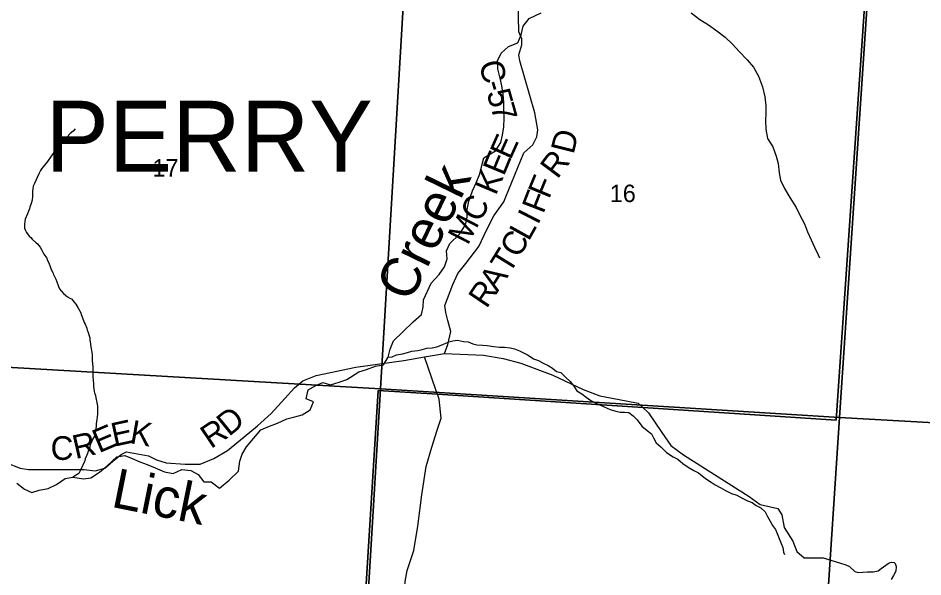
# Model space of a CAD drawing. Extents: x 0 to 34, y 0 to 22.
# Drawn here: x 3.885 to 6.056, y 18.575 to 19.917 of the extents above; entities that cross this region are included whole.
import ezdxf

# ---------------------------------------------------------------- set-up
doc = ezdxf.new("R2010")
doc.units = 0
for name, color, linetype in [('GM_X_County_Road', 7, 'Continuous'), ('GM_X_County_Road_Text', 7, 'Continuous'), ('GM_X_Minor_River', 7, 'Continuous'), ('GM_X_Minor_River_Text', 7, 'Continuous'), ('GM_X_Section', 7, 'Continuous'), ('GM_X_Section_Text', 7, 'Continuous'), ('GM_X_Township', 7, 'Continuous'), ('GM_X_Township_Road', 7, 'Continuous'), ('GM_X_Township_Text', 7, 'Continuous')]:
    doc.layers.add(name, color=color, linetype=linetype)

msp = doc.modelspace()

# ---------------------------------------------------------------- linework, layer by layer
at = {"layer": 'GM_X_County_Road'}
for points in [[(4.9082, 19.1111), (4.9163, 19.1327), (4.9235, 19.1639), (4.9163, 19.1903), (4.9115, 19.2095), (4.9091, 19.2262), (4.9283, 19.2766), (4.9403, 19.303), (4.9595, 19.327), (4.9907, 19.3678), (5.0099, 19.4086), (5.0267, 19.4421), (5.0387, 19.4589), (5.0507, 19.4757), (5.0555, 19.4877), (5.0986, 19.5932), (5.1202, 19.6124), (5.1298, 19.6316), (5.1322, 19.6484), (5.125, 19.6892), (5.089, 19.8139), (5.0867, 19.8283), (5.0939, 19.8522), (5.0939, 19.8666), (5.0867, 19.8834), (5.0839, 19.9908)], [(3.8568, 18.8491), (3.8896, 18.836), (3.9093, 18.8328), (4.0435, 18.8327), (4.0698, 18.8295), (4.0927, 18.836), (4.1123, 18.8524), (4.132, 18.8688), (4.1451, 18.8753), (4.1975, 18.8655), (4.2171, 18.8557), (4.24, 18.8491), (4.2859, 18.8458), (4.3219, 18.8458), (4.3547, 18.8589), (4.3875, 18.8785), (4.4268, 18.9113), (4.4595, 18.9375), (4.4923, 18.967), (4.525, 19.003), (4.5479, 19.0292), (4.5676, 19.0456), (4.6003, 19.0587), (4.6953, 19.0783), (4.81, 19.0947), (4.8596, 19.103), (4.9082, 19.1111), (5.0013, 19.1069), (5.0492, 19.0992), (5.0913, 19.0877), (5.1679, 19.059), (5.2407, 19.0246), (5.2809, 19.0093), (5.344, 18.9978), (5.3728, 18.992), (5.3841, 18.9816), (5.3977, 18.9691), (5.43, 18.9217)], [(5.43, 18.9217), (5.4512, 18.8906), (5.4819, 18.8676), (5.6389, 18.7681), (5.6657, 18.749), (5.6906, 18.7432), (5.7078, 18.7394), (5.7174, 18.7241), (5.7231, 18.6935), (5.7442, 18.6609), (5.7537, 18.636), (5.771, 18.6207), (5.8169, 18.6207), (5.8564, 18.609), (5.8711, 18.6042), (5.88, 18.5999), (5.8925, 18.5881), (5.9012, 18.5856), (5.923, 18.587), (5.9371, 18.587), (5.9492, 18.5897), (5.9562, 18.5947), (5.967, 18.603), (5.9749, 18.6088), (5.9807, 18.61), (5.9869, 18.6092), (5.9898, 18.6067), (5.9919, 18.5997), (5.9911, 18.5889), (5.9857, 18.5785), (5.9803, 18.569)]]:
    msp.add_lwpolyline(points, dxfattribs=at)
at = {"layer": 'GM_X_Minor_River'}
for points in [[(4.0982, 18.8415), (4.1218, 18.8635), (4.1407, 18.8664), (4.1581, 18.8595), (4.177, 18.8511), (4.1944, 18.845), (4.2133, 18.8365), (4.236, 18.8273), (4.2564, 18.8235), (4.2776, 18.8325), (4.2988, 18.8301), (4.317, 18.821), (4.3305, 18.8034), (4.348, 18.8034), (4.3683, 18.7881), (4.3911, 18.807), (4.4132, 18.829), (4.4171, 18.8525), (4.4225, 18.8699), (4.4331, 18.8874), (4.4499, 18.907), (4.4674, 18.9282), (4.4879, 18.9365), (4.5068, 18.944), (4.5296, 18.9546), (4.5486, 18.9591), (4.566, 18.9643), (4.5857, 18.9764), (4.5934, 18.9954), (4.576, 19.0022), (4.5806, 19.0243), (4.5989, 19.0341), (4.6163, 19.0416), (4.6345, 19.0362), (4.6549, 19.0422), (4.6739, 19.049), (4.702, 19.0671), (4.721, 19.0731), (4.7422, 19.0806), (4.7619, 19.0843), (4.7726, 19.1025), (4.7772, 19.1215), (4.7856, 19.142), (4.8077, 19.1631), (4.8328, 19.1874), (4.8525, 19.2047), (4.8571, 19.2222), (4.8572, 19.2404), (4.8756, 19.2798), (4.8953, 19.301), (4.9083, 19.3192), (4.9144, 19.3382), (4.913, 19.3579), (4.9206, 19.3753), (4.9442, 19.398), (4.9587, 19.42), (4.9626, 19.4382), (4.9626, 19.4572), (4.9665, 19.4769), (4.975, 19.5019), (4.9841, 19.5209), (4.9925, 19.5429), (4.9972, 19.5626), (5.0026, 19.5808), (5.0306, 19.5982), (5.0436, 19.6179), (5.0475, 19.6353), (5.0506, 19.6558), (5.0514, 19.6763), (5.0507, 19.6953), (5.0501, 19.7135), (5.0486, 19.734), (5.0457, 19.7537), (5.042, 19.7727), (5.036, 19.7948), (5.0353, 19.8138), (5.0437, 19.8327), (5.062, 19.8486), (5.084, 19.8569), (5.0924, 19.8766), (5.097, 19.897), (5.1115, 19.9152), (5.1403, 19.9288)], [(5.5001, 19.9291), (5.5212, 19.9131)], [(5.5212, 19.9131), (5.5416, 19.9001), (5.5613, 19.8856), (5.5816, 19.8704), (5.599, 19.8536), (5.6163, 19.8353), (5.6344, 19.8163), (5.6495, 19.7988), (5.6615, 19.7775), (5.6713, 19.7516), (5.6772, 19.7273), (5.6794, 19.7061), (5.6793, 19.6886), (5.6785, 19.6704), (5.6792, 19.6499), (5.6829, 19.6271), (5.6957, 19.6073), (5.7039, 19.5853), (5.7091, 19.5678), (5.7113, 19.545), (5.7143, 19.5275), (5.724, 19.5077), (5.7368, 19.4857), (5.7519, 19.4621), (5.7609, 19.4431), (5.7721, 19.4225), (5.7796, 19.4035), (5.7879, 19.3838), (5.7961, 19.3663), (5.8052, 19.348), (5.8082, 19.3412)], [(4.0214, 19.6503), (4.0167, 19.6454), (4.0098, 19.6395), (4.0063, 19.6361), (4.0028, 19.6305), (3.9994, 19.6264), (3.9947, 19.6208), (3.9874, 19.614), (3.9832, 19.6103), (3.9797, 19.6062), (3.9766, 19.6009), (3.9708, 19.595), (3.9677, 19.5905), (3.961, 19.5803), (3.958, 19.577), (3.9552, 19.5724), (3.9479, 19.5635), (3.9444, 19.5597), (3.9405, 19.5545), (3.9385, 19.5503), (3.9342, 19.5428), (3.9303, 19.5341), (3.9271, 19.5266), (3.9236, 19.5191), (3.9208, 19.5127), (3.9196, 19.5066), (3.9191, 19.5009), (3.9194, 19.4948), (3.9193, 19.4888), (3.918, 19.4797), (3.916, 19.4717), (3.9128, 19.4623), (3.9119, 19.4585), (3.9092, 19.4532), (3.9068, 19.4468), (3.9013, 19.434), (3.9004, 19.4283), (3.8999, 19.4219), (3.8995, 19.4166), (3.9001, 19.412), (3.9019, 19.4066), (3.9045, 19.4017), (3.9108, 19.3928), (3.9153, 19.3897), (3.9186, 19.3859), (3.9279, 19.377), (3.9313, 19.3743), (3.9376, 19.3665), (3.9412, 19.3597), (3.9464, 19.3501), (3.9534, 19.3405), (3.9541, 19.337), (3.9589, 19.3267), (3.9614, 19.3198), (3.9643, 19.3129), (3.968, 19.3057), (3.9686, 19.3022), (3.9749, 19.2896), (3.9778, 19.2831), (3.9799, 19.277), (3.9818, 19.2724), (3.9843, 19.2666), (3.988, 19.2616), (3.9936, 19.2551), (4.0029, 19.2473), (4.0089, 19.2438), (4.0127, 19.2422), (4.0194, 19.2349), (4.0234, 19.2295), (4.0282, 19.2218), (4.0348, 19.2088), (4.0362, 19.2046), (4.038, 19.1996), (4.0435, 19.1859), (4.0457, 19.1813), (4.0497, 19.1717), (4.0504, 19.1675), (4.0522, 19.1641), (4.0565, 19.1492), (4.0564, 19.1431), (4.0578, 19.1393), (4.0591, 19.1275), (4.0602, 19.1229), (4.0605, 19.1188), (4.0622, 19.1089), (4.0625, 19.1024), (4.0627, 19.0948), (4.0636, 19.0796), (4.0639, 19.0739), (4.0641, 19.0674), (4.0643, 19.0556), (4.0649, 19.0469), (4.0655, 19.0385), (4.0658, 19.0321), (4.0664, 19.0264), (4.0671, 19.0203), (4.0682, 19.0168), (4.0703, 19.0103), (4.0714, 19.005), (4.0734, 18.9936), (4.0745, 18.9894)], [(4.7726, 19.1025), (4.7821, 19.1034), (4.7931, 19.1079), (4.8071, 19.1102), (4.8188, 19.1136), (4.8298, 19.1166), (4.8438, 19.1188), (4.854, 19.1207), (4.8657, 19.1237), (4.8786, 19.1252), (4.8895, 19.1271), (4.9039, 19.1328), (4.9183, 19.1389), (4.9281, 19.1415), (4.9394, 19.143), (4.9538, 19.1399), (4.9644, 19.1392), (4.9757, 19.1346), (4.9856, 19.1319), (4.9988, 19.1312), (5.0105, 19.1304), (5.0264, 19.1281), (5.0404, 19.1262), (5.0517, 19.1262), (5.0653, 19.1246), (5.0763, 19.1227), (5.0884, 19.1174), (5.099, 19.1121), (5.1092, 19.1071), (5.1217, 19.0988), (5.1334, 19.0946), (5.1466, 19.087), (5.1572, 19.0828), (5.167, 19.0763), (5.1769, 19.0684), (5.1871, 19.0653), (5.1988, 19.0543), (5.2094, 19.044), (5.2184, 19.0326), (5.226, 19.0213), (5.2377, 19.0144), (5.2479, 19.0064), (5.2592, 18.9988), (5.2706, 18.9928), (5.2808, 18.9882), (5.2914, 18.9832), (5.3054, 18.9768), (5.3193, 18.9726), (5.3299, 18.9703), (5.3401, 18.9703), (5.3507, 18.9699), (5.3605, 18.9619), (5.3707, 18.9517), (5.3817, 18.9372), (5.3946, 18.9262), (5.4048, 18.9182), (5.4097, 18.9084), (5.4161, 18.8966), (5.427, 18.8875), (5.4407, 18.8738), (5.4569, 18.8632), (5.4679, 18.8579), (5.4803, 18.8472), (5.4928, 18.8385), (5.5064, 18.8301), (5.5174, 18.8244), (5.5348, 18.8115), (5.548, 18.8024), (5.5578, 18.7963), (5.5714, 18.7891), (5.5828, 18.7822), (5.5967, 18.7754), (5.61, 18.7712), (5.624, 18.7632), (5.6349, 18.7575), (5.6463, 18.7537), (5.6561, 18.7461), (5.6671, 18.7404), (5.6776, 18.7309), (5.6829, 18.7203), (5.6897, 18.7085), (5.695, 18.6986), (5.7022, 18.6888), (5.7067, 18.6789), (5.7116, 18.6671), (5.7158, 18.6554), (5.7199, 18.6455), (5.7218, 18.6345), (5.7237, 18.6284)], [(4.0745, 18.9894), (4.0748, 18.9844), (4.0748, 18.9658), (4.0747, 18.9594), (4.0735, 18.9529), (4.0722, 18.9427), (4.0717, 18.9363), (4.0699, 18.923), (4.0691, 18.9181), (4.0671, 18.9113), (4.0624, 18.9038), (4.0616, 18.9), (4.0576, 18.8924), (4.0571, 18.886), (4.0548, 18.8815), (4.0516, 18.8747), (4.0508, 18.8713), (4.0496, 18.8671), (4.048, 18.8637), (4.0457, 18.8585), (4.044, 18.8513), (4.0405, 18.8456), (4.0385, 18.8392), (4.035, 18.8336), (4.0338, 18.8294), (4.0303, 18.823), (4.0163, 18.8145)], [(3.8814, 18.7998), (3.8995, 18.7853), (3.9177, 18.7777), (3.9351, 18.7829), (3.9571, 18.7874), (3.9768, 18.7964), (3.9973, 18.8115), (4.0163, 18.8145), (4.0413, 18.8106), (4.0594, 18.8128), (4.0799, 18.8264), (4.0982, 18.8415)]]:
    msp.add_lwpolyline(points, dxfattribs=at)
at = {"layer": 'GM_X_Section'}
for points in [[(4.8149, 20.0525), (4.754, 19.0266), (3.6625, 19.0898), (3.731, 20.118)], [(5.9246, 19.9867), (5.8561, 18.9573), (4.754, 19.0266), (4.8149, 20.0525)], [(7.0324, 19.92), (6.9681, 18.8952), (5.8561, 18.9573), (5.9246, 19.9867)], [(3.6625, 19.0898), (4.754, 19.0266), (4.6942, 18.026), (3.5959, 18.098)], [(4.754, 19.0266), (5.8561, 18.9573), (5.7907, 17.959), (4.6942, 18.026)], [(5.8561, 18.9573), (6.9681, 18.8952), (6.9079, 17.8893), (5.7907, 17.959)]]:
    msp.add_lwpolyline(points, close=True, dxfattribs=at)
at = {"layer": 'GM_X_Township'}
for points in [[(5.9855, 20.8908), (5.9767, 20.7996), (5.9657, 20.645), (5.923, 20.0446), (5.9184, 19.9792), (5.8482, 18.9514), (5.3841, 18.9816), (4.8908, 19.0136), (4.7488, 19.0228), (4.6863, 18.0158)], [(4.6863, 18.0158), (4.7488, 19.0228), (4.8908, 19.0136), (5.3841, 18.9816), (5.8482, 18.9514), (5.9184, 19.9792), (5.923, 20.0446), (5.9657, 20.645), (5.9767, 20.7996), (5.9855, 20.8908)]]:
    msp.add_lwpolyline(points, dxfattribs=at)
at = {"layer": 'GM_X_Township_Road'}
for points in [[(4.8872, 19.0239), (4.8596, 19.103)], [(4.8416, 18.3803), (4.8347, 18.421), (4.8158, 18.4639), (4.8094, 18.5083), (4.8135, 18.5638), (4.8181, 18.59), (4.8344, 18.6382), (4.8439, 18.697), (4.8537, 18.7722), (4.8636, 18.8398), (4.8772, 18.8865), (4.8905, 18.927), (4.8996, 18.9558), (4.8951, 19.0015), (4.8908, 19.0136), (4.8873, 19.0236), (4.8872, 19.0239)]]:
    msp.add_lwpolyline(points, dxfattribs=at)

# ---------------------------------------------------------------- texts
at = {"layer": 'GM_X_County_Road_Text'}
for s, rotation, p in [('C', 283.0308, (4.9907, 19.8088)), ('-', 286.0474, (5.0021, 19.7601)), ('5', 285.9904, (5.0085, 19.7377)), ('7', 285.6604, (5.0181, 19.7042)), ('E', 65.8064, (5.0666, 19.5741)), ('D', 75.9454, (5.2175, 19.5877)), ('E', 67.5026, (5.0505, 19.5353)), ('R', 53.1987, (5.179, 19.5282)), ('K', 67.1785, (5.031, 19.4889)), ('F', 67.4881, (5.1588, 19.4802)), ('F', 68.855, (5.1451, 19.4448)), ('C', 60.4093, (4.9919, 19.4234)), ('M', 62.4774, (4.9637, 19.3692)), ('I', 63.0784, (5.132, 19.4182)), ('L', 60.9576, (5.1102, 19.3791)), ('C', 60.4905, (5.087, 19.338)), ('T', 58.2888, (5.0635, 19.2998)), ('A', 56.779, (5.0352, 19.2566)), ('R', 56.2249, (5.0089, 19.2173)), ('D', 39.1121, (4.3906, 18.9105)), ('E', 23.1261, (4.0785, 18.8714)), ('E', 12.4015, (4.1149, 18.8872)), ('K', 350.0485, (4.1506, 18.8962)), ('R', 33.8016, (4.3472, 18.8812)), ('R', 12.6834, (4.0222, 18.8577)), ('C', 0.9251, (3.963, 18.8554))]:
    msp.add_text(s, height=0.0568, rotation=rotation, dxfattribs=at).set_placement(p)
at = {"layer": 'GM_X_Minor_River_Text'}
for s, height, rotation, p in [('Creek', 0.09468, 64.0091, (4.8256, 19.2312)), ('Lick', 0.0947, 348.6135, (4.1052, 18.7437))]:
    msp.add_text(s, height=height, rotation=rotation, dxfattribs=at).set_placement(p)
at = {"layer": 'GM_X_Section_Text'}
for s, p in [('17', (4.2073, 19.5361)), ('16', (5.3048, 19.4748))]:
    msp.add_text(s, height=0.04186, rotation=0, dxfattribs=at).set_placement(p)
at = {"layer": 'GM_X_Township_Text'}
msp.add_text('PERRY', height=0.17045, rotation=0, dxfattribs=at).set_placement((3.9502, 19.5476))

doc.saveas('drawing.dxf')
